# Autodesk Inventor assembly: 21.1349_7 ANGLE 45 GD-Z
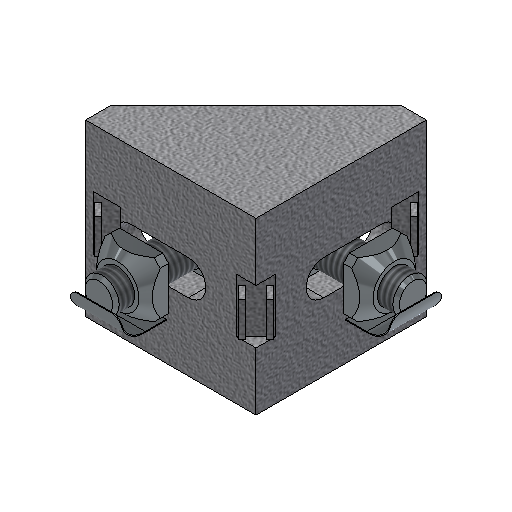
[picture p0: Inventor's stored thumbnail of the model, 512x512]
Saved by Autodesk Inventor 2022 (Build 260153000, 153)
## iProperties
Created: 2007-01
Part Number: 21.1349_7 ANGLE 45 GD-Z
Document SubType Name: Assembly
Designer: Andy Moles
Mass: 103.815 g
Surface Area: 216.075 cm^2
Volume: 32.2164 cm^3
Density: 3.22241 g/cm^3
Description: ANGLE 45 GD-Z
Author: Andy Moles
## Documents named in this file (5)
- L:\INVENTOR LIBRARIES\PARTS LIBRARY\FASTENING ELEMENTS\21.1349_7 ANGLE 45 GD-Z.iam
- L:\INVENTOR LIBRARIES\PARTS LIBRARY\FASTENING ELEMENTS\SUBCOMPONENTS\21.1349 ANGLE 45 GD-Z.ipt
- L:\INVENTOR LIBRARIES\PARTS LIBRARY\FASTENING ELEMENTS\WASHERS\21.1127 M8 ROUND WASHER.ipt
- L:\INVENTOR LIBRARIES\PARTS LIBRARY\FASTENING ELEMENTS\SCREWS CAP\21.1280 M8X22.ipt
- L:\INVENTOR LIBRARIES\PARTS LIBRARY\FASTENING ELEMENTS\NUTS\21.1351_2 M8 SQUARE NUT POS FXG.ipt
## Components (7 placed, 4 different names)
1. 21.1349 ANGLE 45 GD-Z:1 — Flush:1, Flush:2, Mate:1, Mate:2, Mate:3, Mate:4, Mate:5, Mate:6, Mate:7, Mate:10, Mate:11, Angle:1, Angle:2
2. 21.1280 M8X22:2 — Insert:1, Mate:2, Mate:4, Mate:9
3. 21.1280 M8X22:1 — Insert:2, Mate:6, Mate:7, Mate:8
4. 21.1127 M8 ROUND WASHER — Insert:1, Mate:3
5. 21.1127 M8 ROUND WASHER:2 — Insert:2, Mate:5
6. 21.1351_2 M8 SQUARE NUT POS FXG:1 — Mate:8, Mate:11, Angle:2
7. 21.1351_2 M8 SQUARE NUT POS FXG:2 — Mate:9, Mate:10, Angle:1
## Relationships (17: Mate 11, Flush 2, Insert 2, Angle 2)
- Flush:1: 21.1349 ANGLE 45 GD-Z:1
- Flush:2: 21.1349 ANGLE 45 GD-Z:1
- Mate:1: 21.1349 ANGLE 45 GD-Z:1
- Insert:1: 21.1280 M8X22:2 ↔ 21.1127 M8 ROUND WASHER
- Insert:2: 21.1280 M8X22:1 ↔ 21.1127 M8 ROUND WASHER:2
- Mate:2: 21.1349 ANGLE 45 GD-Z:1 ↔ 21.1280 M8X22:2
- Mate:3: 21.1349 ANGLE 45 GD-Z:1 ↔ 21.1127 M8 ROUND WASHER
- Mate:4: 21.1349 ANGLE 45 GD-Z:1 ↔ 21.1280 M8X22:2
- Mate:5: 21.1349 ANGLE 45 GD-Z:1 ↔ 21.1127 M8 ROUND WASHER:2
- Mate:6: 21.1349 ANGLE 45 GD-Z:1 ↔ 21.1280 M8X22:1
- Mate:7: 21.1349 ANGLE 45 GD-Z:1 ↔ 21.1280 M8X22:1
- Mate:8: 21.1280 M8X22:1 ↔ 21.1351_2 M8 SQUARE NUT POS FXG:1
- Mate:9: 21.1280 M8X22:2 ↔ 21.1351_2 M8 SQUARE NUT POS FXG:2
- Mate:10: 21.1349 ANGLE 45 GD-Z:1 ↔ 21.1351_2 M8 SQUARE NUT POS FXG:2
- Mate:11: 21.1349 ANGLE 45 GD-Z:1 ↔ 21.1351_2 M8 SQUARE NUT POS FXG:1
- Angle:1: 21.1349 ANGLE 45 GD-Z:1 ↔ 21.1351_2 M8 SQUARE NUT POS FXG:2
- Angle:2: 21.1349 ANGLE 45 GD-Z:1 ↔ 21.1351_2 M8 SQUARE NUT POS FXG:1
